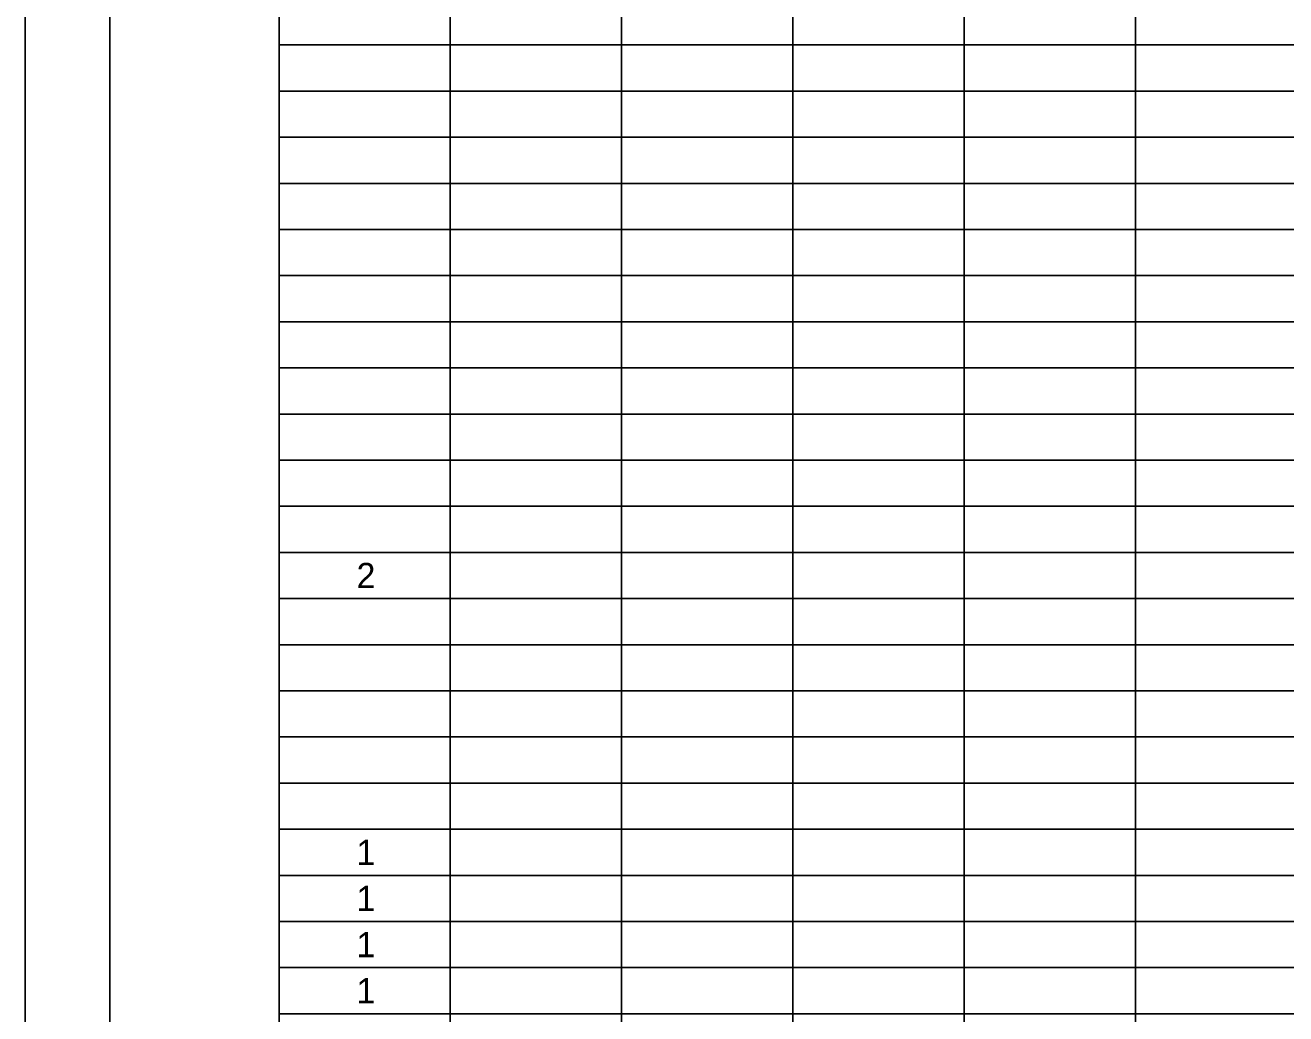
# Model space of a CAD drawing. Extents: x 0 to 34, y 0 to 22.
# Drawn here: x 0 to 7.45, y 10.33 to 16.17 of the extents above; entities that cross this region are included whole.
import ezdxf

# ---------------------------------------------------------------- set-up
doc = ezdxf.new("R2010")
doc.units = 0
for name, color, linetype in [('Default', 7, 'Continuous'), ('SH_Border', 7, 'Continuous'), ('SH_Cut_Line', 7, 'Continuous')]:
    doc.layers.add(name, color=color, linetype=linetype)

msp = doc.modelspace()

# ---------------------------------------------------------------- linework, layer by layer
at = {"layer": 'Default'}
for p, q in [((1.5, 16.3215), (1.5, 16.0489)), ((2.5123, 16.3215), (2.5123, 16.0489)), ((3.5247, 16.3215), (3.5247, 16.0489)), ((4.537, 16.3215), (4.537, 16.0489)), ((5.5494, 16.3215), (5.5494, 16.0489)), ((6.5617, 16.3215), (6.5617, 16.0489)), ((1.5, 16.0489), (6.5617, 16.0489)), ((1.5, 16.0489), (1.5, 15.7764)), ((2.5123, 16.0489), (2.5123, 15.7764)), ((3.5247, 16.0489), (3.5247, 15.7764)), ((4.537, 16.0489), (4.537, 15.7764)), ((5.5494, 16.0489), (5.5494, 15.7764)), ((6.5617, 16.0489), (7.574, 16.0489)), ((6.5617, 16.0489), (6.5617, 15.7764)), ((1.5, 15.7764), (6.5617, 15.7764)), ((1.5, 15.7764), (1.5, 15.5038)), ((2.5123, 15.7764), (2.5123, 15.5038)), ((3.5247, 15.7764), (3.5247, 15.5038)), ((4.537, 15.7764), (4.537, 15.5038)), ((5.5494, 15.7764), (5.5494, 15.5038)), ((6.5617, 15.7764), (7.574, 15.7764)), ((6.5617, 15.7764), (6.5617, 15.5038)), ((1.5, 15.5038), (6.5617, 15.5038)), ((1.5, 15.5038), (1.5, 14.9587)), ((2.5123, 15.5038), (2.5123, 14.9587)), ((3.5247, 15.5038), (3.5247, 14.9587)), ((4.537, 15.5038), (4.537, 14.9587)), ((5.5494, 15.5038), (5.5494, 14.9587)), ((6.5617, 15.5038), (7.574, 15.5038)), ((6.5617, 15.5038), (6.5617, 14.9587)), ((1.5, 15.2313), (6.5617, 15.2313)), ((6.5617, 15.2313), (7.574, 15.2313)), ((1.5, 14.9587), (6.5617, 14.9587)), ((1.5, 14.9587), (1.5, 14.6862)), ((2.5123, 14.9587), (2.5123, 14.6862)), ((3.5247, 14.9587), (3.5247, 14.6862)), ((4.537, 14.9587), (4.537, 14.6862)), ((5.5494, 14.9587), (5.5494, 14.6862)), ((6.5617, 14.9587), (7.574, 14.9587)), ((6.5617, 14.9587), (6.5617, 14.6862)), ((1.5, 14.6862), (6.5617, 14.6862)), ((1.5, 14.6862), (1.5, 14.4136)), ((2.5123, 14.6862), (2.5123, 14.4136)), ((3.5247, 14.6862), (3.5247, 14.4136)), ((4.537, 14.6862), (4.537, 14.4136)), ((5.5494, 14.6862), (5.5494, 14.4136)), ((6.5617, 14.6862), (7.574, 14.6862)), ((6.5617, 14.6862), (6.5617, 14.4136)), ((1.5, 14.4136), (6.5617, 14.4136)), ((1.5, 14.4136), (1.5, 14.1411)), ((2.5123, 14.4136), (2.5123, 14.1411)), ((3.5247, 14.4136), (3.5247, 14.1411)), ((4.537, 14.4136), (4.537, 14.1411)), ((5.5494, 14.4136), (5.5494, 14.1411)), ((6.5617, 14.4136), (7.574, 14.4136)), ((6.5617, 14.4136), (6.5617, 14.1411)), ((1.5, 14.1411), (6.5617, 14.1411)), ((1.5, 14.1411), (1.5, 11.9606)), ((2.5123, 14.1411), (2.5123, 11.9606)), ((3.5247, 14.1411), (3.5247, 11.9606)), ((4.537, 14.1411), (4.537, 11.9606)), ((5.5494, 14.1411), (5.5494, 11.9606)), ((6.5617, 14.1411), (7.574, 14.1411)), ((6.5617, 14.1411), (6.5617, 11.9606)), ((1.5, 13.8685), (6.5617, 13.8685)), ((6.5617, 13.8685), (7.574, 13.8685)), ((1.5, 13.596), (6.5617, 13.596)), ((6.5617, 13.596), (7.574, 13.596)), ((1.5, 13.3234), (6.5617, 13.3234)), ((6.5617, 13.3234), (7.574, 13.3234)), ((1.5, 13.0509), (6.5617, 13.0509)), ((6.5617, 13.0509), (7.574, 13.0509)), ((1.5, 12.7783), (6.5617, 12.7783)), ((6.5617, 12.7783), (7.574, 12.7783)), ((1.5, 12.5057), (6.5617, 12.5057)), ((6.5617, 12.5057), (7.574, 12.5057)), ((1.5, 12.2332), (6.5617, 12.2332)), ((6.5617, 12.2332), (7.574, 12.2332)), ((1.5, 11.9606), (6.5617, 11.9606)), ((1.5, 11.9606), (1.5, 11.6881)), ((2.5123, 11.9606), (2.5123, 11.6881)), ((3.5247, 11.9606), (3.5247, 11.6881)), ((4.537, 11.9606), (4.537, 11.6881)), ((5.5494, 11.9606), (5.5494, 11.6881)), ((6.5617, 11.9606), (7.574, 11.9606)), ((6.5617, 11.9606), (6.5617, 11.6881)), ((1.5, 11.6881), (6.5617, 11.6881)), ((1.5, 11.6881), (1.5, 10.5979)), ((2.5123, 11.6881), (2.5123, 10.5979)), ((3.5247, 11.6881), (3.5247, 10.5979)), ((4.537, 11.6881), (4.537, 10.5979)), ((5.5494, 11.6881), (5.5494, 10.5979)), ((6.5617, 11.6881), (7.574, 11.6881)), ((6.5617, 11.6881), (6.5617, 10.5979)), ((1.5, 11.4155), (6.5617, 11.4155)), ((6.5617, 11.4155), (7.574, 11.4155)), ((1.5, 11.143), (6.5617, 11.143)), ((6.5617, 11.143), (7.574, 11.143)), ((1.5, 10.8704), (6.5617, 10.8704)), ((6.5617, 10.8704), (7.574, 10.8704)), ((1.5, 10.5979), (6.5617, 10.5979)), ((1.5, 10.5979), (1.5, 10.3253)), ((2.5123, 10.5979), (2.5123, 10.3253)), ((3.5247, 10.5979), (3.5247, 10.3253)), ((4.537, 10.5979), (4.537, 10.3253)), ((5.5494, 10.5979), (5.5494, 10.3253)), ((6.5617, 10.5979), (7.574, 10.5979)), ((6.5617, 10.5979), (6.5617, 10.3253)), ((1.5, 10.3253), (6.5617, 10.3253)), ((1.5, 10.3253), (1.5, 10.0528)), ((2.5123, 10.3253), (2.5123, 10.0528)), ((3.5247, 10.3253), (3.5247, 10.0528)), ((4.537, 10.3253), (4.537, 10.0528)), ((5.5494, 10.3253), (5.5494, 10.0528)), ((6.5617, 10.3253), (7.574, 10.3253)), ((6.5617, 10.3253), (6.5617, 10.0528))]:
    msp.add_line(p, q, dxfattribs=at)
at = {"layer": 'SH_Border'}
for points in [[(0.5, 21.5), (1.5, 21.5), (1.5, 0.5), (0.5, 0.5)], [(1.5, 21.5), (33.5, 21.5), (33.5, 0.5), (1.5, 0.5)]]:
    msp.add_lwpolyline(points, close=True, dxfattribs=at)
at = {"layer": 'SH_Cut_Line'}
msp.add_lwpolyline([(0, 0), (34, 0), (34, 22), (0, 22)], close=True, dxfattribs=at)

# ---------------------------------------------------------------- texts
at = {"layer": 'Default'}
for s, p in [('2', (1.9584, 12.8399)), ('1', (1.9583, 11.2046)), ('1', (1.9583, 10.9321)), ('1', (1.9583, 10.6595)), ('1', (1.9583, 10.387))]:
    msp.add_text(s, height=0.1493, dxfattribs=at).set_placement(p)

doc.saveas('drawing.dxf')
